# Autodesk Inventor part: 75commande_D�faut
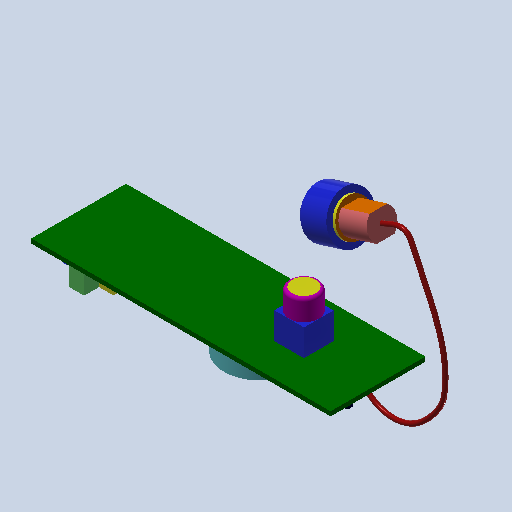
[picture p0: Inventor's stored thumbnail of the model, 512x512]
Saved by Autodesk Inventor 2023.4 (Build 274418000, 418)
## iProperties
Created: 2011-01
Part Number: 75commande_D�faut
Document SubType Name: Modeling
Designer: eric
Density: 1 g/cm^3
Mass: 15.0932 g
Surface Area: 111.425 cm^2
Volume: 15.0932 cm^3
Material: Générique
Appearance: 255,128,0
Author: eric
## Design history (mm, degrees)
feature "Base1"
node "Corps solides"
node "Corps surfaciques"
node "Solide1"
